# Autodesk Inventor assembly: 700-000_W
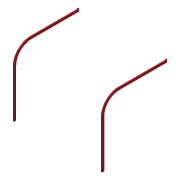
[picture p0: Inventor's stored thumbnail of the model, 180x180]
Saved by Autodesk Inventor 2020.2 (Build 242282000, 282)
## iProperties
Created: 2018-01
Part Number: 700-000_W
Document SubType Name: Assembly
Designer: F.Stasiak
Manager: www.cadconsulting.pl
Company: Fabian Stasiak CAD Consulting
Author: F.Stasiak
Subject: Zbiór ćwiczeń. Autodesk Inventor 2020. Kurs podstawowy
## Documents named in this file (2)
- C:\2020_Kurs_podstawowy\R6 Zespoły\Wiązania\Brama\700-000_BRAMA.iam
- C:\2020_Kurs_podstawowy\R6 Zespoły\Wiązania\Brama\700-001.ipt
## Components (2 placed, 1 different names)
1. 700-001:1
2. 700-001:2
